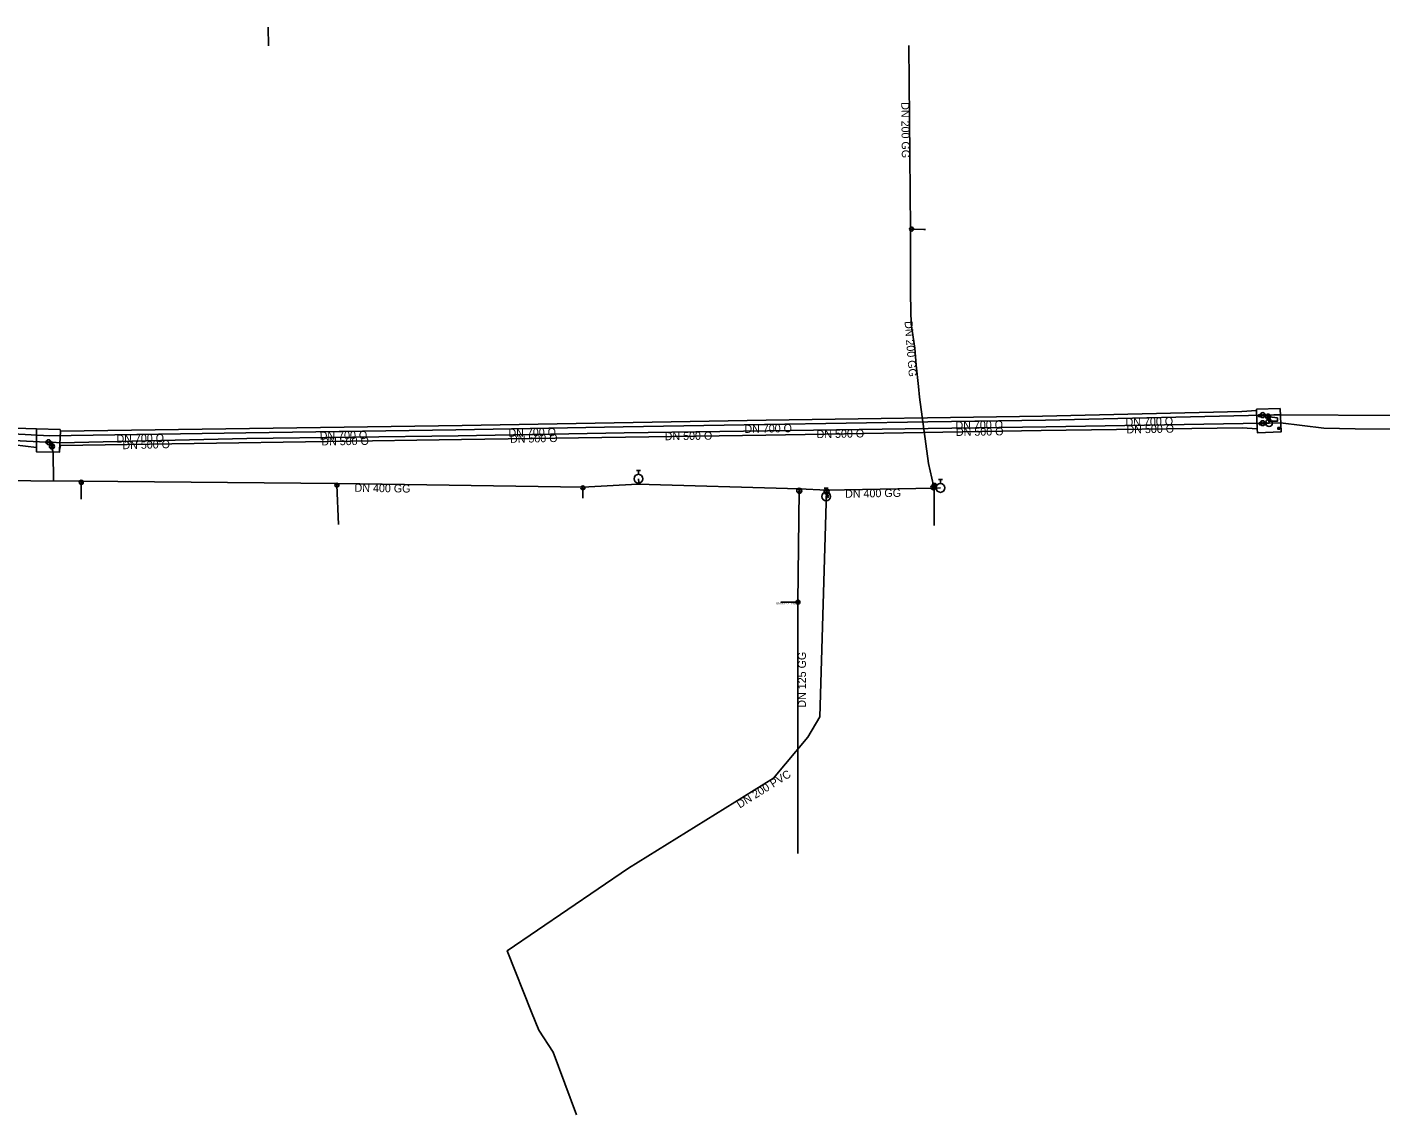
# Model space of a CAD drawing. Extents: x -451355 to -449353, y -1101368 to -1101089.
# Drawn here: x -450409.1 to -450137.6, y -1101368.3 to -1101150.2 of the extents above; entities that cross this region are included whole.
import ezdxf

# ---------------------------------------------------------------- set-up
doc = ezdxf.new("R2010")
doc.units = 0
for name, color, linetype in [('_hydrantova_odbocka_', 7, 'Continuous'), ('_kalosvod_', 7, 'Continuous'), ('_kolektor_', 7, 'Continuous'), ('_pripojka_prevzato_z_dokumentace_', 7, 'Continuous'), ('_pripojka_priblizne_', 7, 'Continuous'), ('_voda_smvak_prevzato_z_dokumentace_', 7, 'Continuous'), ('_voda_smvak_priblizne_', 7, 'Continuous'), ('Default', 7, 'Continuous'), ('MoLevel 27', 7, 'Continuous'), ('MoLevel 28', 7, 'Continuous'), ('MoLevel 30', 7, 'Continuous'), ('MoLevel 32', 7, 'Continuous'), ('MoLevel 42', 7, 'Continuous'), ('MoLevel 46', 7, 'Continuous'), ('MoLevel 53', 7, 'Continuous')]:
    doc.layers.add(name, color=color, linetype=linetype)

# ---------------------------------------------------------------- blocks, each defined once
blk = doc.blocks.new('_uzaver_')
at = {"layer": 'Default'}
for p, q in [((-0.000035, -0.000035), (0.000035, 0.000035)), ((0.000035, -0.000035), (-0.000035, 0.000035))]:
    blk.add_line(p, q, dxfattribs=at)
for radius in [0.00005, 0.0000025]:
    blk.add_circle((0, 0), radius, dxfattribs=at)
blk = doc.blocks.new('_uzaver_pripojka_')
at = {"layer": 'Default'}
for p, q in [((-0.000035, -0.000035), (0.000035, 0.000035)), ((0.000035, -0.000035), (-0.000035, 0.000035))]:
    blk.add_line(p, q, dxfattribs=at)
for radius in [0.00005, 0.0000025]:
    blk.add_circle((0, 0), radius, dxfattribs=at)
blk = doc.blocks.new('_hydrant_voda_')
at = {"layer": 'Default'}
for p, q in [((-0.000023, 0.000095), (0.000023, 0.000095)), ((0, 0.000095), (0, 0.00005))]:
    blk.add_line(p, q, dxfattribs=at)
blk.add_circle((0, 0), 0.00005, dxfattribs=at)
blk = doc.blocks.new('_sachta_voda_')
at = {"layer": 'Default'}
blk.add_circle((0, 0), 0.000035, dxfattribs=at)
blk = doc.blocks.new('_poklop_voda_')
at = {"layer": 'Default'}
blk.add_lwpolyline([(-0.00002, 0.000015), (0.00002, 0.000015), (0.00002, -0.000015), (-0.00002, -0.000015), (-0.00002, 0.000015)], dxfattribs=at)

msp = doc.modelspace()

# ---------------------------------------------------------------- linework, layer by layer
at = {"layer": '_hydrantova_odbocka_'}
for p, q in [((-450286.68, -1101241.85), (-450286.46, -1101241.55)), ((-450286.46, -1101241.55), (-450286.52, -1101240.78))]:
    msp.add_line(p, q, dxfattribs=at)
msp.add_lwpolyline([(-450248.78, -1101243.37), (-450248.62, -1101244.3), (-450248.87, -1101244.33)], dxfattribs=at)
at = {"layer": '_kalosvod_'}
for points in [[(-450161.92, -1101228.12), (-450161.92, -1101228.28), (-450161.92, -1101228.28), (-450161.92, -1101228.28)], [(-450160.87, -1101228.1), (-450160.87, -1101228.28), (-450160.87, -1101228.28)], [(-450161.8, -1101229.73), (-450161.8, -1101229.93), (-450161.8, -1101229.93)], [(-450160.8, -1101229.7), (-450160.8, -1101229.85), (-450160.8, -1101229.85)]]:
    msp.add_lwpolyline(points, dxfattribs=at)
at = {"layer": '_kolektor_'}
for points in [[(-450491.55, -1101228.73), (-450411.99, -1101233.64), (-450411.68, -1101234.01), (-450407.22, -1101234.54), (-450407.25, -1101230.81), (-450411.53, -1101230.63), (-450411.87, -1101230.98), (-450491.38, -1101225.92), (-450569.3, -1101220.42), (-450631.44, -1101216.56), (-450644.66, -1101215.78), (-450644.83, -1101218.45), (-450631.61, -1101219.35), (-450569.49, -1101223.22)], [(-450157.8, -1101226.68), (-450162.55, -1101226.85), (-450162.54, -1101227.13), (-450162.41, -1101230.75), (-450162.38, -1101231.56), (-450157.63, -1101231.39)], [(-450402.44, -1101234.15), (-450321.98, -1101232.93), (-450260.98, -1101232.07), (-450205.78, -1101231.11), (-450165.46, -1101230.58), (-450162.41, -1101230.75), (-450162.54, -1101227.13), (-450165.53, -1101227.33), (-450205.51, -1101228.27), (-450260.88, -1101229.05), (-450321.88, -1101230.11), (-450402.41, -1101231.22), (-450402.6, -1101235.07)], [(-450159.98, -1101228.35), (-450158.38, -1101228.58), (-450158.36, -1101229.27), (-450159.87, -1101229.21)], [(-450402.47, -1101230.88), (-450407.25, -1101230.81), (-450407.22, -1101234.54), (-450407.21, -1101235.39), (-450402.61, -1101235.44), (-450402.6, -1101235.07), (-450402.41, -1101231.22)]]:
    msp.add_lwpolyline(points, close=True, dxfattribs=at)
at = {"layer": '_pripojka_prevzato_z_dokumentace_'}
for points in [[(-450231.95, -1101190.69), (-450231.74, -1101190.73), (-450229.26, -1101190.79), (-450228.94, -1101190.8)], [(-450398.26, -1101241.29), (-450398.25, -1101241.49), (-450398.25, -1101244.9)], [(-450346.86, -1101241.73), (-450347, -1101242.09), (-450346.7, -1101249.97)], [(-450297.69, -1101242.48), (-450297.67, -1101242.62), (-450297.66, -1101244.69)], [(-450227.33, -1101242.12), (-450227.18, -1101242.11), (-450227.18, -1101250.17)]]:
    msp.add_lwpolyline(points, dxfattribs=at)
at = {"layer": '_pripojka_priblizne_'}
for p, q in [((-450360.78, -1101150.22), (-450360.69, -1101154.01)), ((-450254.53, -1101265.53), (-450257.95, -1101265.53))]:
    msp.add_line(p, q, dxfattribs=at)
at = {"layer": '_voda_smvak_prevzato_z_dokumentace_'}
for p, q in [((-450232.32, -1101153.91), (-450231.95, -1101190.69)), ((-450228.48, -1101229.37), (-450204.89, -1101229.01)), ((-450204.89, -1101229.01), (-450161.31, -1101228.03)), ((-450204.75, -1101230.36), (-450161.31, -1101229.64)), ((-450161.31, -1101228.03), (-450160.28, -1101228.01)), ((-450161.31, -1101229.64), (-450160.04, -1101229.62)), ((-450160.28, -1101228.01), (-450159.07, -1101227.99)), ((-450160.28, -1101228.01), (-450160.23, -1101228.33)), ((-450160.23, -1101228.33), (-450160.04, -1101229.62)), ((-450160.04, -1101229.62), (-450157.74, -1101229.56)), ((-450159.07, -1101227.99), (-450157.79, -1101227.95)), ((-450411.98, -1101231.78), (-450404.62, -1101232.17)), ((-450404.62, -1101232.17), (-450365.28, -1101231.57)), ((-450365.28, -1101231.57), (-450323.12, -1101230.95)), ((-450322.7, -1101232.17), (-450365.03, -1101232.69)), ((-450323.12, -1101230.95), (-450289.56, -1101230.39)), ((-450322.7, -1101232.17), (-450289.36, -1101231.57)), ((-450289.36, -1101231.57), (-450260.64, -1101231.21)), ((-450260.64, -1101231.21), (-450228.44, -1101230.68)), ((-450228.44, -1101230.68), (-450204.75, -1101230.36)), ((-450411.85, -1101233.11), (-450405.3, -1101233.46)), ((-450405.3, -1101233.46), (-450404.84, -1101233.45)), ((-450404.84, -1101233.45), (-450404.49, -1101233.45)), ((-450404.49, -1101233.45), (-450404.06, -1101233.44)), ((-450404.06, -1101233.44), (-450404.15, -1101234.29)), ((-450404.06, -1101233.44), (-450402.51, -1101233.56)), ((-450402.51, -1101233.56), (-450365.03, -1101232.69)), ((-450254.28, -1101242.82), (-450248.76, -1101243.06)), ((-450254.28, -1101242.82), (-450254.27, -1101243.19)), ((-450248.78, -1101243.37), (-450248.76, -1101243.06)), ((-450227.35, -1101242.7), (-450248.76, -1101243.06)), ((-450227.35, -1101242.49), (-450227.35, -1101242.7)), ((-450225.96, -1101242.63), (-450227.35, -1101242.7))]:
    msp.add_line(p, q, dxfattribs=at)
for points in [[(-450231.95, -1101190.69), (-450231.94, -1101203.55), (-450231.92, -1101207.09), (-450231.82, -1101209.73), (-450231.11, -1101214.6), (-450230.84, -1101218.01), (-450230.36, -1101222.28), (-450230.14, -1101224.44), (-450228.36, -1101237.71)], [(-450289.56, -1101230.39), (-450261.23, -1101229.93), (-450228.48, -1101229.37)], [(-450157.79, -1101227.95), (-450087.83, -1101228.34)], [(-450157.74, -1101229.56), (-450149.08, -1101230.67), (-450142.79, -1101230.8), (-450132.2, -1101230.86), (-450123.68, -1101231), (-450119.47, -1101231.11), (-450111.15, -1101230.92), (-450097.13, -1101230.65), (-450077.24, -1101230.4), (-450073.21, -1101230.11), (-450068.42, -1101229.99), (-450061.21, -1101229.58), (-450059.76, -1101229.61), (-450055.48, -1101228.82), (-450050.32, -1101228.11)], [(-450404.15, -1101234.29), (-450404.18, -1101234.62), (-450403.88, -1101235.43)], [(-450228.36, -1101237.71), (-450227.33, -1101242.12), (-450227.35, -1101242.49)], [(-450254.28, -1101242.82), (-450286.68, -1101241.85), (-450297.69, -1101242.48), (-450346.86, -1101241.73), (-450398.26, -1101241.29), (-450418.57, -1101241.13)], [(-450254.27, -1101243.19), (-450254.53, -1101265.56), (-450254.54, -1101315.94)], [(-450298.94, -1101368.35), (-450303.64, -1101355.79), (-450306.48, -1101351.38), (-450307.94, -1101347.74), (-450312.85, -1101335.46), (-450288.48, -1101318.89), (-450259.43, -1101300.83), (-450252.56, -1101292.6), (-450250.11, -1101288.54), (-450248.78, -1101243.37)]]:
    msp.add_lwpolyline(points, dxfattribs=at)
at = {"layer": '_voda_smvak_priblizne_'}
msp.add_line((-450403.88, -1101235.43), (-450403.84, -1101241.25), dxfattribs=at)

# ---------------------------------------------------------------- block references
at = {"layer": 'MoLevel 27'}
for p, xscale, yscale, rotation in [((-450161.92, -1101228.12), 5000.000000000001, 5000, 92.4938552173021), ((-450161.8, -1101229.73), 5000.000000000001, 5000.000000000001, -83.088772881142), ((-450160.87, -1101228.1), 4999.999999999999, 5000, 88.25344232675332), ((-450160.8, -1101229.7), 5000, 5000, -80.99149625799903), ((-450160.23, -1101228.33), 10000, 9999.999999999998, -80.40686573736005), ((-450404.15, -1101234.3), 10000, 10000, -81.14569181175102), ((-450254.27, -1101243.19), 10000.000000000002, 10000, -90.64197986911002), ((-450248.78, -1101243.37), 10000, 9999.999999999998, -91.634166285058), ((-450227.35, -1101242.49), 10000, 10000, 86.960810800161)]:
    msp.add_blockref('_uzaver_', p, dxfattribs=dict(at, xscale=xscale, yscale=yscale, rotation=rotation))
for p, xscale, yscale in [((-450161.31, -1101228.03), 10000, 10000), ((-450161.31, -1101229.64), 10000, 10000), ((-450404.84, -1101233.45), 10000, 10000), ((-450248.62, -1101244.3), 5000, 5000)]:
    msp.add_blockref('_uzaver_', p, dxfattribs=dict(at, xscale=xscale, yscale=yscale))
at = {"layer": 'MoLevel 28', "xscale": 17636.68430335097, "yscale": 17636.68430335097}
for p in [(-450286.52, -1101240.78), (-450248.87, -1101244.33), (-450225.96, -1101242.63)]:
    msp.add_blockref('_hydrant_voda_', p, dxfattribs=at)
at = {"layer": 'MoLevel 30', "xscale": 20000, "yscale": 20000}
msp.add_blockref('_sachta_voda_', (-450160.04, -1101229.62), dxfattribs=at)
at = {"layer": 'MoLevel 42', "xscale": 10000, "yscale": 10000}
msp.add_blockref('_poklop_voda_', (-450158.11, -1101230.67), dxfattribs=at)
at = {"layer": 'MoLevel 53', "xscale": 7999.999999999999, "yscale": 7999.999999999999}
for p in [(-450231.74, -1101190.73), (-450398.25, -1101241.49), (-450347, -1101242.09), (-450297.67, -1101242.62), (-450227.18, -1101242.11), (-450254.53, -1101265.53)]:
    msp.add_blockref('_uzaver_pripojka_', p, dxfattribs=at)

# ---------------------------------------------------------------- texts
at = {"layer": 'MoLevel 32'}
msp.add_text("DN 50 - 2'' PE", height=0.455, rotation=0.0889, dxfattribs=at).set_placement((-450258.95, -1101265.99))
at = {"layer": 'MoLevel 46'}
for s, rotation, p in [('DN 200 GG', 270.5764, (-450233.81, -1101165.29)), ('DN 200 GG', 274.5272, (-450233.15, -1101209.23)), ('DN 700 O', 0.8743, (-450222.93, -1101230.89)), ('DN 700 O', 1.2842, (-450188.81, -1101230.25)), ('DN 700 O', 0.8738, (-450391.19, -1101233.57)), ('DN 700 O', 0.8425, (-450350.44, -1101232.96)), ('DN 500 O', 0.7038, (-450350.11, -1101234.11)), ('DN 700 O', 0.956, (-450312.58, -1101232.38)), ('DN 500 O', 1.031, (-450312.27, -1101233.59)), ('DN 500 O', 0.7182, (-450281.25, -1101233.07)), ('DN 700 O', 0.9796, (-450265.26, -1101231.6)), ('DN 500 O', 0.943, (-450250.78, -1101232.65)), ('DN 500 O', 0.7739, (-450222.84, -1101232.21)), ('DN 500 O', 0.9482, (-450188.63, -1101231.7)), ('DN 500 O', 1.3297, (-450390, -1101234.87)), ('DN 400 GG', 359.1261, (-450343.46, -1101243.39)), ('DN 400 GG', 0.9633, (-450245.06, -1101244.6)), ('DN 125 GG', 89.9886, (-450252.93, -1101286.69)), ('DN 200 PVC', 31.8687, (-450266.2, -1101306.93))]:
    msp.add_text(s, height=1.605, rotation=rotation, dxfattribs=at).set_placement(p)

doc.saveas('drawing.dxf')
